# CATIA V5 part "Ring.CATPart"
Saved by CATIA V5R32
Part number: Part1.1
Bounding box of the stored display mesh (mm): x -5 to 5, y -15 to 15, z -15 to 15
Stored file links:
  D:\PROJECTS\Project 2022\CATIA V5 6R 2022\Resources\Part Files\c12_catia_v5_6r2022_prt\c12_catia_v5-6r2022 figr_12-12\Ring.CATPart
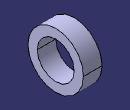
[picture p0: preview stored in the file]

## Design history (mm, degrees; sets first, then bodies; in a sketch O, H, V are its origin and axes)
Body1 (main body)
  Sketch1 on yz-plane, origin (0, 0, 0), H (0, 1, 0), V (0, 0, 1)
    circle A1 centre (0, 0) radius 15
    circle A2 centre (0, 0) radius 10
    radius A1 = 15
    radius A2 = 10
  Pad1: profile Sketch1, direction (1, 0, 0), length 5, mirrored extent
